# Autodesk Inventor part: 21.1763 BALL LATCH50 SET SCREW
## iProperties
Created: 2007-03
Part Number: 21.1763 BALL LATCH50 SET SCREW
Document SubType Name: Modeling
Designer: Andy Moles
Material: Steel
Density: 7.85 g/cm^3
Author: Andy Moles
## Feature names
1. Extrusion1
2. Extrusion2
